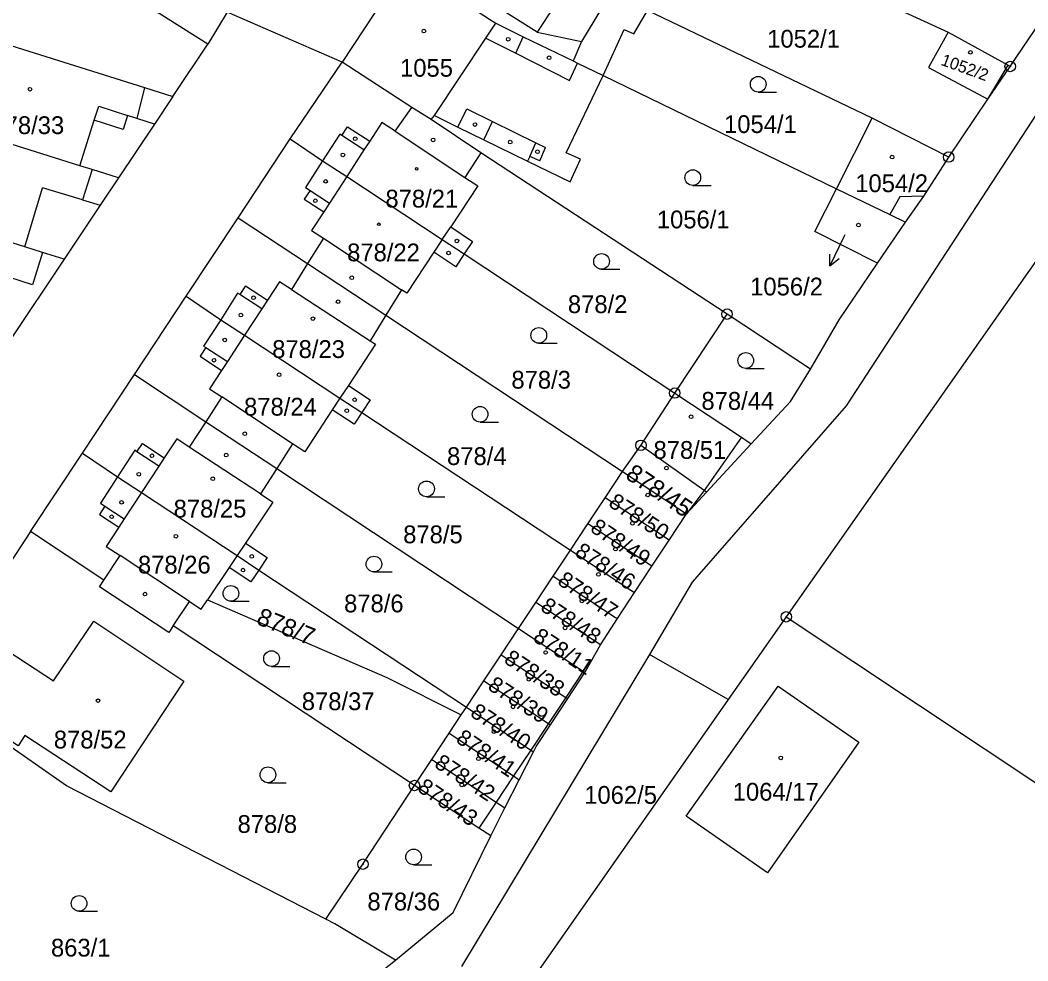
# Model space of a CAD drawing. Extents: x -733394 to -722299, y -1082822 to -1075049.
# Drawn here: x -727749.9 to -727653.6, y -1079652.7 to -1079562.8 of the extents above; entities that cross this region are included whole.
import ezdxf

# ---------------------------------------------------------------- set-up
doc = ezdxf.new("R2010")
doc.units = 0
for name, color, linetype in [('Hranice parcel', 7, 'Continuous'), ('Parcelní čísla', 7, 'Continuous'), ('Pop  PČ popisy', 7, 'Continuous'), ('Vnitřní kresba', 7, 'Continuous'), ('Značky bodu BP', 7, 'Continuous'), ('Značky budov', 7, 'Continuous'), ('Značky kultur', 7, 'Continuous')]:
    doc.layers.add(name, color=color, linetype=linetype)

msp = doc.modelspace()

# ---------------------------------------------------------------- linework, layer by layer
at = {"layer": 'Hranice parcel'}
for p, q in [((-727686.16, -1079552.54), (-727661.25, -1079563.98)), ((-727713.03, -1079557.56), (-727719.16, -1079566.85)), ((-727730.14, -1079562.07), (-727731.98, -1079565.14)), ((-727719.16, -1079566.85), (-727730.14, -1079562.07)), ((-727668.49, -1079572.22), (-727689.97, -1079561.93)), ((-727735.32, -1079570.14), (-727731.98, -1079565.14)), ((-727724.11, -1079574.18), (-727719.16, -1079566.85)), ((-727657.44, -1079570.39), (-727655.31, -1079567.27)), ((-727694.22, -1079568.12), (-727671.92, -1079578.95)), ((-727661.19, -1079575.93), (-727657.44, -1079570.39)), ((-727705.91, -1079575.53), (-727710.65, -1079572.34)), ((-727671.92, -1079578.95), (-727668.49, -1079572.22)), ((-727661.19, -1079575.93), (-727668.49, -1079572.22)), ((-727729.09, -1079581.72), (-727724.11, -1079574.18)), ((-727682.37, -1079590.94), (-727705.91, -1079575.53)), ((-727734.05, -1079589.22), (-727729.09, -1079581.72)), ((-727745.71, -1079585.69), (-727750.91, -1079593.46)), ((-727707.48, -1079585.18), (-727687.37, -1079598.48)), ((-727739, -1079596.72), (-727734.05, -1079589.22)), ((-727714.97, -1079591.04), (-727692.35, -1079605.99)), ((-727687.37, -1079598.48), (-727682.37, -1079590.94)), ((-727674.39, -1079596.2), (-727682.37, -1079590.94)), ((-727743.97, -1079604.22), (-727739, -1079596.72)), ((-727690.6, -1079603.48), (-727687.37, -1079598.48)), ((-727717.27, -1079600.34), (-727697.32, -1079613.49)), ((-727692.35, -1079605.99), (-727690.6, -1079603.48)), ((-727684.33, -1079607.96), (-727680.08, -1079603.32)), ((-727748.93, -1079611.73), (-727743.97, -1079604.22)), ((-727725.41, -1079605.7), (-727702.29, -1079620.99)), ((-727694.01, -1079608.49), (-727692.35, -1079605.99)), ((-727692.35, -1079605.99), (-727686.24, -1079610.04)), ((-727686.24, -1079610.04), (-727684.33, -1079607.96)), ((-727695.66, -1079610.99), (-727694.01, -1079608.49)), ((-727687.9, -1079612.54), (-727694.01, -1079608.49)), ((-727687.9, -1079612.54), (-727686.24, -1079610.04)), ((-727697.32, -1079613.49), (-727695.66, -1079610.99)), ((-727689.56, -1079615.03), (-727695.66, -1079610.99)), ((-727689.56, -1079615.03), (-727687.9, -1079612.54)), ((-727698.98, -1079615.99), (-727697.32, -1079613.49)), ((-727727.11, -1079615.4), (-727707.27, -1079628.49)), ((-727691.22, -1079617.53), (-727689.56, -1079615.03)), ((-727700.64, -1079618.5), (-727698.98, -1079615.99)), ((-727685.71, -1079616.56), (-727689.78, -1079623.46)), ((-727692.85, -1079620.04), (-727691.22, -1079617.53)), ((-727702.29, -1079620.99), (-727700.64, -1079618.5)), ((-727694.48, -1079622.56), (-727700.64, -1079618.5)), ((-727694.48, -1079622.56), (-727692.85, -1079620.04)), ((-727676.71, -1079619.87), (-727682.25, -1079627.77)), ((-727676.71, -1079619.87), (-727636.48, -1079646.67)), ((-727712.24, -1079635.99), (-727735.3, -1079620.74)), ((-727703.95, -1079623.49), (-727702.29, -1079620.99)), ((-727695.95, -1079625.19), (-727694.48, -1079622.56)), ((-727689.78, -1079623.46), (-727707.76, -1079653.3)), ((-727705.61, -1079625.99), (-727703.95, -1079623.49)), ((-727682.25, -1079627.77), (-727689.78, -1079623.46)), ((-727697.6, -1079627.69), (-727695.95, -1079625.19)), ((-727707.27, -1079628.49), (-727705.61, -1079625.99)), ((-727682.25, -1079627.77), (-727704.95, -1079660.15)), ((-727699.25, -1079630.2), (-727697.6, -1079627.69)), ((-727707.77, -1079629.25), (-727707.27, -1079628.49)), ((-727708.92, -1079630.99), (-727707.77, -1079629.25)), ((-727710.58, -1079633.49), (-727708.92, -1079630.99)), ((-727702.23, -1079635.44), (-727700.87, -1079632.76)), ((-727712.24, -1079635.99), (-727710.58, -1079633.49)), ((-727703.6, -1079638.13), (-727702.23, -1079635.44)), ((-727704.96, -1079640.81), (-727703.6, -1079638.13))]:
    msp.add_line(p, q, dxfattribs=at)
for points in [[(-727567.39, -1079493.16), (-727570.02, -1079494.77), (-727587.58, -1079512.34), (-727596.77, -1079519.98), (-727628.39, -1079564.69), (-727634.86, -1079560.19), (-727676.71, -1079619.87)], [(-727624.36, -1079537.96), (-727639.61, -1079547.11), (-727646.55, -1079562.23), (-727670.98, -1079599.7), (-727685.71, -1079616.56)], [(-727731.98, -1079565.14), (-727739.31, -1079560.47), (-727747.46, -1079555.9)], [(-727713.03, -1079557.56), (-727705.08, -1079562.75), (-727704.48, -1079563.14), (-727701.85, -1079564.42), (-727697.07, -1079566.73), (-727696.65, -1079566.94), (-727694.22, -1079568.12)], [(-727655.31, -1079567.27), (-727654.75, -1079566.42), (-727649.95, -1079559.35), (-727649.73, -1079558.81)], [(-727694.22, -1079568.12), (-727692.2, -1079563.74), (-727691.29, -1079564.14), (-727689.97, -1079561.93)], [(-727661.25, -1079563.98), (-727663.11, -1079567.36), (-727657.44, -1079570.39)], [(-727661.25, -1079563.98), (-727655.51, -1079567.14), (-727655.31, -1079567.27)], [(-727751.97, -1079564.91), (-727738.04, -1079569.29), (-727735.32, -1079570.14)], [(-727710.65, -1079572.34), (-727712.51, -1079571.2), (-727719.16, -1079566.85)], [(-727710.65, -1079572.34), (-727710.34, -1079571.96), (-727708.09, -1079573.06), (-727705.6, -1079574.28), (-727701.45, -1079576.31), (-727697.35, -1079578.31), (-727696.39, -1079576.13), (-727697.76, -1079575.52), (-727694.22, -1079568.12)], [(-727735.32, -1079570.14), (-727737.09, -1079572.78), (-727740.52, -1079577.91)], [(-727740.52, -1079577.91), (-727743.04, -1079577.12), (-727744.23, -1079576.75), (-727760.93, -1079571.51)], [(-727724.11, -1079574.18), (-727721.02, -1079576.29), (-727718.72, -1079577.79), (-727709.58, -1079583.82), (-727707.48, -1079585.18)], [(-727705.91, -1079575.53), (-727707.44, -1079577.87), (-727706.19, -1079578.69), (-727708.78, -1079582.61), (-727706.7, -1079583.99), (-727707.48, -1079585.18)], [(-727665.33, -1079582.15), (-727663.55, -1079579.65), (-727661.19, -1079575.93)], [(-727740.52, -1079577.91), (-727742.27, -1079580.53), (-727745.71, -1079585.69)], [(-727667.99, -1079586.08), (-727673.99, -1079583.04), (-727671.92, -1079578.95)], [(-727671.92, -1079578.95), (-727666.81, -1079581.43), (-727665.33, -1079582.15)], [(-727745.71, -1079585.69), (-727747.8, -1079585.04), (-727749.48, -1079584.51), (-727759.14, -1079581.49)], [(-727729.09, -1079581.72), (-727722.45, -1079586.11), (-727714.97, -1079591.04)], [(-727667.99, -1079586.08), (-727665.8, -1079582.85), (-727665.33, -1079582.15)], [(-727707.48, -1079585.18), (-727708.3, -1079586.41), (-727710.39, -1079585.03), (-727712.98, -1079588.95), (-727713.48, -1079588.62), (-727714.97, -1079591.04)], [(-727674.39, -1079596.2), (-727671.65, -1079591.47), (-727667.99, -1079586.08)], [(-727734.05, -1079589.22), (-727730.76, -1079591.47), (-727728.48, -1079592.96), (-727719.36, -1079598.96), (-727717.27, -1079600.34)], [(-727714.97, -1079591.04), (-727716.48, -1079593.49), (-727715.98, -1079593.82), (-727718.56, -1079597.75), (-727716.47, -1079599.12), (-727717.27, -1079600.34)], [(-727680.08, -1079603.32), (-727676.3, -1079599.29), (-727674.39, -1079596.2)], [(-727739, -1079596.72), (-727732.18, -1079601.23), (-727725.41, -1079605.7)], [(-727687.37, -1079598.48), (-727680.99, -1079602.71), (-727680.08, -1079603.32)], [(-727717.27, -1079600.34), (-727718.01, -1079601.46), (-727720.1, -1079600.09), (-727722.73, -1079604.1), (-727723.9, -1079603.33), (-727725.41, -1079605.7)], [(-727684.33, -1079607.96), (-727684.55, -1079607.8), (-727690.6, -1079603.48)], [(-727743.97, -1079604.22), (-727740.61, -1079606.48), (-727738.33, -1079607.98), (-727729.2, -1079614.02), (-727727.11, -1079615.4)], [(-727725.41, -1079605.7), (-727726.96, -1079608.13), (-727725.78, -1079608.91), (-727728.39, -1079612.82), (-727726.32, -1079614.21), (-727727.11, -1079615.4)], [(-727748.93, -1079611.73), (-727753.89, -1079619.24), (-727758.85, -1079626.72)], [(-727735.3, -1079620.74), (-727735.71, -1079621.37), (-727742.34, -1079617), (-727741.92, -1079616.36), (-727748.93, -1079611.73)], [(-727697.32, -1079613.49), (-727691.55, -1079617.31), (-727691.22, -1079617.53)], [(-727727.11, -1079615.4), (-727727.87, -1079616.53), (-727729.95, -1079615.14), (-727732.02, -1079618.24)], [(-727698.98, -1079615.99), (-727693.02, -1079619.94), (-727692.85, -1079620.04)], [(-727735.3, -1079620.74), (-727733.75, -1079618.39), (-727732.62, -1079619.13), (-727732.02, -1079618.24)], [(-727732.02, -1079618.24), (-727714.88, -1079625.66), (-727707.77, -1079629.25)], [(-727749.48, -1079631.2), (-727750.13, -1079632.19), (-727756.7, -1079627.87), (-727752.85, -1079622.02), (-727746.74, -1079625.98), (-727742.89, -1079620.29), (-727734.29, -1079626.02), (-727741.27, -1079636.61), (-727749.48, -1079631.2)], [(-727702.29, -1079620.99), (-727696.12, -1079625.07), (-727695.95, -1079625.19)], [(-727703.95, -1079623.49), (-727697.78, -1079627.57), (-727697.6, -1079627.69)], [(-727705.61, -1079625.99), (-727699.44, -1079630.07), (-727699.25, -1079630.2)], [(-727720.71, -1079648.77), (-727745.5, -1079636.01), (-727758.85, -1079626.72)], [(-727686.29, -1079638.92), (-727677.5, -1079626.49), (-727669.78, -1079631.85), (-727678.5, -1079644.33), (-727686.29, -1079638.92)], [(-727707.27, -1079628.49), (-727701.12, -1079632.6), (-727700.87, -1079632.76)], [(-727708.92, -1079630.99), (-727702.77, -1079635.08), (-727702.23, -1079635.44)], [(-727700.87, -1079632.76), (-727700.62, -1079632.27), (-727699.25, -1079630.2)], [(-727710.58, -1079633.49), (-727704.43, -1079637.58), (-727703.6, -1079638.13)], [(-727720.71, -1079648.77), (-727717.17, -1079643.51), (-727712.24, -1079635.99)], [(-727704.96, -1079640.81), (-727706.08, -1079640.07), (-727712.24, -1079635.99)], [(-727714.04, -1079652.7), (-727708.56, -1079648.12), (-727704.96, -1079640.81)], [(-727714.04, -1079652.7), (-727719.84, -1079649.22), (-727720.71, -1079648.77)], [(-727726.36, -1079666.77), (-727725.02, -1079665.91), (-727719.36, -1079656.88), (-727714.04, -1079652.7)]]:
    msp.add_lwpolyline(points, dxfattribs=at)
at = {"layer": 'Pop  PČ popisy'}
for p, q in [((-727671.23, -1079583.62), (-727672.546, -1079586.317)), ((-727671.1, -1079583.35), (-727671.23, -1079583.62)), ((-727672.546, -1079586.317), (-727672.557, -1079585.198)), ((-727672.546, -1079586.317), (-727671.656, -1079585.637))]:
    msp.add_line(p, q, dxfattribs=at)
at = {"layer": 'Vnitřní kresba'}
for p, q in [((-727696.96, -1079558.52), (-727700.51, -1079563.98)), ((-727693.46, -1079560.23), (-727696.27, -1079564.89)), ((-727700.51, -1079563.98), (-727704.38, -1079561.56)), ((-727705.42, -1079564.55), (-727704.48, -1079563.14)), ((-727710.34, -1079571.96), (-727705.42, -1079564.55)), ((-727705.42, -1079564.55), (-727702.54, -1079566.01)), ((-727702.54, -1079566.01), (-727701.85, -1079564.42)), ((-727700.51, -1079563.98), (-727696.27, -1079564.89)), ((-727696.27, -1079564.89), (-727697.02, -1079566.61)), ((-727702.54, -1079566.01), (-727697.42, -1079568.62)), ((-727697.02, -1079566.61), (-727697.07, -1079566.73)), ((-727697.42, -1079568.62), (-727696.65, -1079566.94)), ((-727657.44, -1079570.39), (-727655.51, -1079567.14)), ((-727738.04, -1079569.29), (-727738.77, -1079572.24)), ((-727742.84, -1079572.4), (-727742.41, -1079571.07)), ((-727742.41, -1079571.07), (-727739.67, -1079571.95)), ((-727714.09, -1079573.46), (-727712.51, -1079571.2)), ((-727708.09, -1079573.06), (-727707.24, -1079571.32)), ((-727707.24, -1079571.32), (-727704.8, -1079572.52)), ((-727744.23, -1079576.75), (-727742.84, -1079572.4)), ((-727740.09, -1079573.28), (-727742.84, -1079572.4)), ((-727739.67, -1079571.95), (-727740.09, -1079573.28)), ((-727738.77, -1079572.24), (-727739.67, -1079571.95)), ((-727737.09, -1079572.78), (-727738.77, -1079572.24)), ((-727719.18, -1079573.88), (-727718.63, -1079573.03)), ((-727718.63, -1079573.03), (-727716.52, -1079574.4)), ((-727715.36, -1079572.63), (-727716.52, -1079574.4)), ((-727714.09, -1079573.46), (-727715.36, -1079572.63)), ((-727705.6, -1079574.28), (-727704.8, -1079572.52)), ((-727704.8, -1079572.52), (-727700.66, -1079574.56)), ((-727719.39, -1079573.74), (-727721.02, -1079576.29)), ((-727719.18, -1079573.88), (-727719.39, -1079573.74)), ((-727717.07, -1079575.25), (-727719.18, -1079573.88)), ((-727714.09, -1079573.46), (-727707.44, -1079577.87)), ((-727717.07, -1079575.25), (-727718.72, -1079577.79)), ((-727716.52, -1079574.4), (-727717.07, -1079575.25)), ((-727701.23, -1079575.86), (-727700.66, -1079574.56)), ((-727700.66, -1079574.56), (-727699.72, -1079575.02)), ((-727700.27, -1079576.28), (-727699.72, -1079575.02)), ((-727701.23, -1079575.86), (-727701.45, -1079576.31)), ((-727700.27, -1079576.28), (-727701.23, -1079575.86)), ((-727743.04, -1079577.12), (-727743.97, -1079580.02)), ((-727721.02, -1079576.29), (-727722.65, -1079578.84)), ((-727718.72, -1079577.79), (-727720.37, -1079580.32)), ((-727749.48, -1079584.51), (-727747.78, -1079578.87)), ((-727743.97, -1079580.02), (-727747.78, -1079578.87)), ((-727722.22, -1079579.11), (-727722.78, -1079579.96)), ((-727722.65, -1079578.84), (-727722.22, -1079579.11)), ((-727722.22, -1079579.11), (-727720.37, -1079580.32)), ((-727743.97, -1079580.02), (-727742.27, -1079580.53)), ((-727722.78, -1079579.96), (-727720.92, -1079581.17)), ((-727665.85, -1079579.72), (-727666.81, -1079581.43)), ((-727663.55, -1079579.65), (-727665.85, -1079579.72)), ((-727720.37, -1079580.32), (-727720.92, -1079581.17)), ((-727720.92, -1079581.17), (-727722.07, -1079582.94)), ((-727722.07, -1079582.94), (-727720.93, -1079583.68)), ((-727709.58, -1079583.82), (-727708.78, -1079582.61)), ((-727720.93, -1079583.68), (-727722.45, -1079586.11)), ((-727720.93, -1079583.68), (-727713.48, -1079588.62)), ((-727709.58, -1079583.82), (-727710.39, -1079585.03)), ((-727747.8, -1079585.04), (-727748.74, -1079588.15)), ((-727722.45, -1079586.11), (-727724, -1079588.58)), ((-727748.74, -1079588.15), (-727752.59, -1079586.89)), ((-727728.38, -1079588.23), (-727728.93, -1079589.07)), ((-727728.38, -1079588.23), (-727726.28, -1079589.6)), ((-727725.13, -1079587.84), (-727726.28, -1079589.6)), ((-727724, -1079588.58), (-727725.13, -1079587.84)), ((-727724, -1079588.58), (-727716.48, -1079593.49)), ((-727729.14, -1079588.93), (-727730.76, -1079591.47)), ((-727728.93, -1079589.07), (-727729.14, -1079588.93)), ((-727726.83, -1079590.44), (-727728.93, -1079589.07)), ((-727726.28, -1079589.6), (-727726.83, -1079590.44)), ((-727726.83, -1079590.44), (-727728.48, -1079592.96)), ((-727730.76, -1079591.47), (-727732.39, -1079594)), ((-727728.48, -1079592.96), (-727730.12, -1079595.48)), ((-727732.18, -1079594.13), (-727732.72, -1079594.97)), ((-727732.39, -1079594), (-727732.18, -1079594.13)), ((-727732.18, -1079594.13), (-727730.12, -1079595.48)), ((-727732.72, -1079594.97), (-727730.67, -1079596.32)), ((-727730.12, -1079595.48), (-727730.67, -1079596.32)), ((-727730.67, -1079596.32), (-727731.82, -1079598.08)), ((-727731.82, -1079598.08), (-727730.64, -1079598.85)), ((-727718.56, -1079597.75), (-727719.36, -1079598.96)), ((-727730.64, -1079598.85), (-727732.18, -1079601.23)), ((-727723.9, -1079603.33), (-727730.64, -1079598.85)), ((-727719.36, -1079598.96), (-727720.1, -1079600.09)), ((-727732.18, -1079601.23), (-727733.76, -1079603.65)), ((-727734.96, -1079602.87), (-727736.15, -1079604.67)), ((-727733.76, -1079603.65), (-727734.96, -1079602.87)), ((-727680.99, -1079602.71), (-727684.55, -1079607.8)), ((-727738.98, -1079603.95), (-727740.61, -1079606.48)), ((-727738.77, -1079604.09), (-727738.98, -1079603.95)), ((-727738.77, -1079604.09), (-727738.24, -1079603.29)), ((-727736.67, -1079605.47), (-727738.77, -1079604.09)), ((-727738.24, -1079603.29), (-727736.15, -1079604.67)), ((-727726.96, -1079608.13), (-727733.76, -1079603.65)), ((-727736.15, -1079604.67), (-727736.67, -1079605.47)), ((-727736.67, -1079605.47), (-727738.33, -1079607.98)), ((-727740.61, -1079606.48), (-727742.25, -1079609.01)), ((-727738.33, -1079607.98), (-727739.98, -1079610.5)), ((-727684.55, -1079607.8), (-727686.24, -1079610.04)), ((-727741.83, -1079609.29), (-727742.35, -1079610.08)), ((-727742.25, -1079609.01), (-727741.83, -1079609.29)), ((-727741.83, -1079609.29), (-727739.98, -1079610.5)), ((-727742.35, -1079610.08), (-727740.51, -1079611.3)), ((-727739.98, -1079610.5), (-727740.51, -1079611.3)), ((-727740.51, -1079611.3), (-727741.72, -1079613.14)), ((-727728.39, -1079612.82), (-727729.2, -1079614.02)), ((-727741.72, -1079613.14), (-727740.38, -1079614.02)), ((-727741.92, -1079616.36), (-727740.38, -1079614.02)), ((-727733.75, -1079618.39), (-727740.38, -1079614.02)), ((-727729.2, -1079614.02), (-727729.95, -1079615.14)), ((-727696.12, -1079625.07), (-727697.78, -1079627.57)), ((-727697.78, -1079627.57), (-727699.44, -1079630.07)), ((-727699.44, -1079630.07), (-727701.12, -1079632.6)), ((-727701.12, -1079632.6), (-727702.77, -1079635.08)), ((-727702.77, -1079635.08), (-727704.43, -1079637.58)), ((-727704.43, -1079637.58), (-727706.08, -1079640.07))]:
    msp.add_line(p, q, dxfattribs=at)
at = {"layer": 'Značky bodu BP'}
for centre, radius in [((-727655.31, -1079567.27), 0.5), ((-727655.31, -1079567.27), 0.0303), ((-727661.19, -1079575.93), 0.5), ((-727661.19, -1079575.93), 0.0303), ((-727682.37, -1079590.94), 0.5), ((-727682.37, -1079590.94), 0.0303), ((-727687.37, -1079598.48), 0.5), ((-727687.37, -1079598.48), 0.0303), ((-727690.6, -1079603.48), 0.5), ((-727690.6, -1079603.48), 0.0303), ((-727676.71, -1079619.87), 0.5), ((-727676.71, -1079619.87), 0.0303), ((-727712.24, -1079635.99), 0.5), ((-727712.24, -1079635.99), 0.0303), ((-727717.17, -1079643.51), 0.5), ((-727717.17, -1079643.51), 0.0303)]:
    msp.add_circle(centre, radius, dxfattribs=at)
at = {"layer": 'Značky budov'}
for centre, radius in [((-727711.347, -1079563.889), 0.175), ((-727703.277, -1079564.659), 0.175), ((-727699.377, -1079566.439), 0.175), ((-727659.117, -1079565.919), 0.175), ((-727748.987, -1079569.449), 0.175), ((-727706.457, -1079572.819), 0.175), ((-727717.907, -1079574.179), 0.175), ((-727710.467, -1079574.289), 0.175), ((-727703.087, -1079574.499), 0.175), ((-727700.487, -1079575.419), 0.175), ((-727719.087, -1079575.719), 0.175), ((-727666.597, -1079575.929), 0.175), ((-727712.035, -1079577.049), 0.122), ((-727720.727, -1079578.249), 0.175), ((-727721.717, -1079580.109), 0.175), ((-727715.645, -1079582.349), 0.122), ((-727669.817, -1079582.429), 0.175), ((-727708.187, -1079583.949), 0.175), ((-727708.987, -1079585.099), 0.175), ((-727718.237, -1079587.459), 0.175), ((-727727.617, -1079589.369), 0.175), ((-727719.537, -1079589.749), 0.175), ((-727728.827, -1079591.029), 0.175), ((-727721.947, -1079591.369), 0.175), ((-727730.377, -1079593.409), 0.175), ((-727731.397, -1079595.339), 0.175), ((-727725.177, -1079596.729), 0.175), ((-727717.957, -1079599.119), 0.175), ((-727718.707, -1079600.179), 0.175), ((-727685.807, -1079600.749), 0.175), ((-727728.457, -1079602.369), 0.175), ((-727737.327, -1079604.479), 0.175), ((-727730.227, -1079604.409), 0.175), ((-727738.587, -1079606.239), 0.175), ((-727688.167, -1079605.659), 0.175), ((-727731.517, -1079606.669), 0.175), ((-727740.237, -1079608.929), 0.175), ((-727689.947, -1079608.229), 0.175), ((-727741.177, -1079610.309), 0.175), ((-727691.417, -1079610.929), 0.175), ((-727735.037, -1079612.169), 0.175), ((-727693.037, -1079613.399), 0.175), ((-727727.787, -1079614.099), 0.175), ((-727728.627, -1079615.399), 0.175), ((-727694.657, -1079615.819), 0.175), ((-727737.997, -1079617.699), 0.175), ((-727696.247, -1079618.349), 0.175), ((-727697.847, -1079620.929), 0.175), ((-727699.707, -1079623.279), 0.175), ((-727701.307, -1079625.839), 0.175), ((-727742.487, -1079627.879), 0.175), ((-727702.827, -1079628.479), 0.175), ((-727704.647, -1079630.849), 0.175), ((-727706.127, -1079633.439), 0.175), ((-727677.237, -1079633.349), 0.175), ((-727707.727, -1079635.939), 0.175)]:
    msp.add_circle(centre, radius, dxfattribs=at)
at = {"layer": 'Značky kultur'}
for p, q in [((-727679.393, -1079569.72), (-727677.643, -1079569.72)), ((-727685.643, -1079578.64), (-727683.893, -1079578.64)), ((-727694.363, -1079586.65), (-727692.613, -1079586.65)), ((-727700.363, -1079593.72), (-727698.613, -1079593.72)), ((-727680.583, -1079596.12), (-727678.833, -1079596.12)), ((-727705.973, -1079601.26), (-727704.223, -1079601.26)), ((-727711.093, -1079608.39), (-727709.343, -1079608.39)), ((-727716.113, -1079615.58), (-727714.363, -1079615.58)), ((-727729.783, -1079618.38), (-727728.033, -1079618.38)), ((-727725.903, -1079624.61), (-727724.153, -1079624.61)), ((-727726.243, -1079635.72), (-727724.493, -1079635.72)), ((-727712.323, -1079643.57), (-727710.573, -1079643.57)), ((-727744.293, -1079648.01), (-727742.543, -1079648.01))]:
    msp.add_line(p, q, dxfattribs=at)
for centre in [(-727679.393, -1079568.97), (-727685.643, -1079577.89), (-727694.363, -1079585.9), (-727700.363, -1079592.97), (-727680.583, -1079595.37), (-727705.973, -1079600.51), (-727711.093, -1079607.64), (-727716.113, -1079614.83), (-727729.783, -1079617.63), (-727725.903, -1079623.86), (-727726.243, -1079634.97), (-727712.323, -1079642.82), (-727744.293, -1079647.26)]:
    msp.add_circle(centre, 0.75, dxfattribs=at)

# ---------------------------------------------------------------- texts
at = {"layer": 'Parcelní čísla'}
for s, p in [('1052/1', (-727678.535, -1079565.47)), ('1055', (-727713.62, -1079568.25)), ('878/33', (-727752.67, -1079573.73)), ('1054/1', (-727682.66, -1079573.63)), ('1054/2', (-727670.12, -1079579.28)), ('878/21', (-727715.02, -1079580.75)), ('1056/1', (-727689.08, -1079582.74)), ('878/22', (-727718.68, -1079585.89)), ('1056/2', (-727680.161, -1079589.153)), ('878/2', (-727697.58, -1079590.84)), ('878/23', (-727725.84, -1079595.13)), ('878/3', (-727702.98, -1079598.06)), ('878/44', (-727684.82, -1079600.08)), ('878/24', (-727728.53, -1079600.64)), ('878/51', (-727689.4, -1079604.77)), ('878/4', (-727709.13, -1079605.36)), ('878/25', (-727735.26, -1079610.38)), ('878/5', (-727713.32, -1079612.84)), ('878/26', (-727738.67, -1079615.73)), ('878/6', (-727718.97, -1079619.44)), ('878/37', (-727723.01, -1079628.79)), ('878/52', (-727746.71, -1079632.45)), ('1062/5', (-727696.02, -1079637.74)), ('1064/17', (-727681.828, -1079637.44)), ('878/8', (-727729.15, -1079640.52)), ('878/36', (-727716.74, -1079647.93)), ('863/1', (-727746.98, -1079652.34))]:
    msp.add_text(s, height=1.7, dxfattribs=at).set_placement(p)
for s, height, rotation, p in [('1052/2', 1.139, 340, (-727662.016, -1079567.097)), ('878/45', 1.7, 326, (-727692.195, -1079606.556)), ('878/50', 1.53, 327, (-727693.806, -1079609.231)), ('878/49', 1.53, 326, (-727695.547, -1079611.634)), ('878/46', 1.53, 327, (-727697.026, -1079613.961)), ('878/47', 1.53, 326, (-727698.677, -1079616.684)), ('878/48', 1.53, 327, (-727700.306, -1079619.191)), ('878/7', 1.7, 338, (-727727.458, -1079620.518)), ('878/11', 1.53, 327, (-727701.026, -1079622.101)), ('878/38', 1.53, 327, (-727703.796, -1079624.191)), ('878/39', 1.53, 327, (-727705.346, -1079626.731)), ('878/40', 1.53, 327, (-727707.016, -1079629.301)), ('878/41', 1.53, 326, (-727708.387, -1079631.774)), ('878/42', 1.53, 327, (-727710.446, -1079634.171)), ('878/43', 1.53, 326, (-727712.057, -1079636.464))]:
    msp.add_text(s, height=height, rotation=rotation, dxfattribs=at).set_placement(p)

doc.saveas('drawing.dxf')
